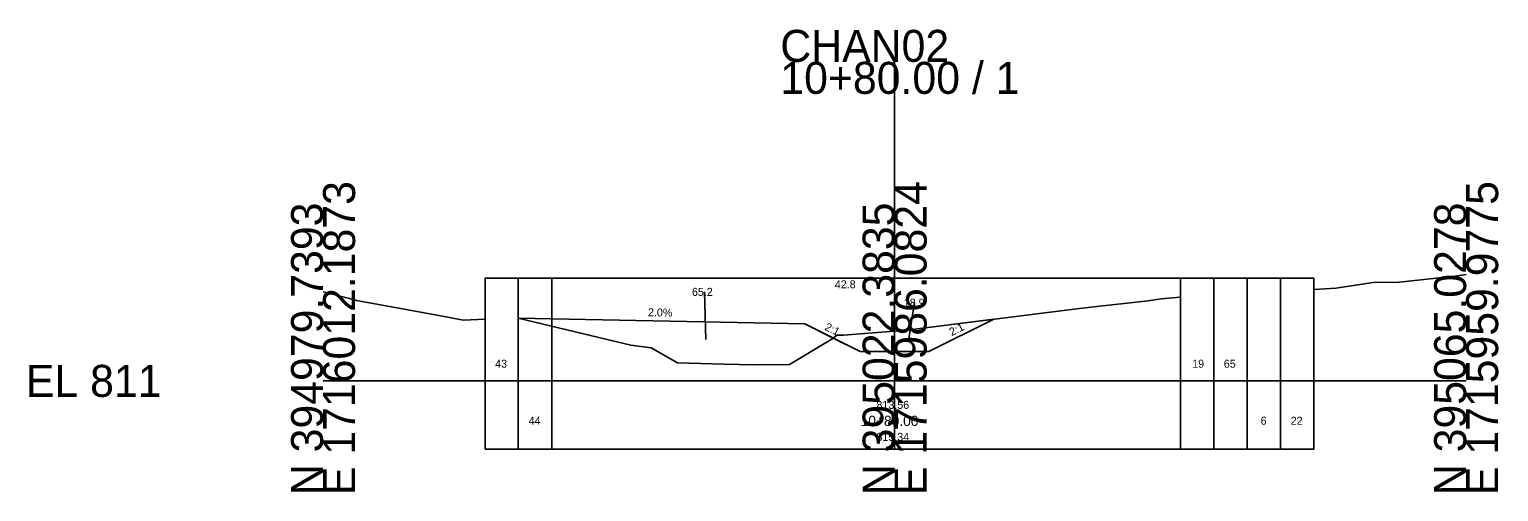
# Model space of a CAD drawing. Extents: x -26 to 103, y -10 to 16052.
# Drawn here: x -25.7 to 102.8, y 10490.3 to 10530.8 of the extents above; entities that cross this region are included whole.
import ezdxf

# ---------------------------------------------------------------- set-up
doc = ezdxf.new("R2010")
doc.units = 0
for name, color, linetype in [('GK_Cells', 7, 'Continuous'), ('SH_Text', 7, 'Continuous'), ('XS_P_Annotation', 7, 'Continuous'), ('XS_P_Boundary', 7, 'Continuous'), ('XS_P_Earthwork_Shapes', 7, 'Continuous'), ('XS_P_Finished_Grade', 7, 'Continuous'), ('XS_X_Ground_Line', 7, 'Continuous')]:
    doc.layers.add(name, color=color, linetype=linetype)

msp = doc.modelspace()

# ---------------------------------------------------------------- linework, layer by layer
at = {"layer": 'GK_Cells'}
for p, q in [((50, 10500), (50, 10527.92)), ((0, 10500), (50, 10500)), ((50, 10500), (100, 10500))]:
    msp.add_line(p, q, dxfattribs=at)
at = {"layer": 'XS_P_Boundary'}
for p, q in [((17.08, 10494.01), (17.08, 10508.99)), ((20, 10494.01), (20, 10508.99)), ((50, 10494.01), (50, 10508.99)), ((75, 10494.01), (75, 10508.99)), ((77.92, 10494.01), (77.92, 10508.99)), ((80.83, 10494.01), (80.83, 10508.99)), ((83.75, 10494.01), (83.75, 10508.99)), ((15.63, 10501.5), (15.63, 10501.5)), ((76.46, 10501.5), (76.46, 10501.5)), ((79.38, 10501.5), (79.38, 10501.5)), ((18.54, 10496.51), (18.54, 10496.51)), ((82.29, 10496.51), (82.29, 10496.51)), ((85.21, 10496.51), (85.21, 10496.51))]:
    msp.add_line(p, q, dxfattribs=at)
msp.add_lwpolyline([(14.17, 10494.01), (14.17, 10508.99), (86.67, 10508.99), (86.67, 10494.01)], close=True, dxfattribs=at)
at = {"layer": 'XS_P_Earthwork_Shapes'}
for p, q in [((33.48, 10503.63), (33.37, 10507.79)), ((51.23, 10503.71), (51.75, 10506.85)), ((42.14, 10504.99), (17.07, 10505.49)), ((44.61, 10503.75), (42.14, 10504.99)), ((58.68, 10505.4), (50.85, 10504.41)), ((53, 10502.56), (58.68, 10505.4)), ((44.63, 10503.74), (47, 10502.56)), ((47, 10502.56), (53, 10502.56))]:
    msp.add_line(p, q, dxfattribs=at)
for points in [[(17.07, 10505.49), (26.93, 10503.12), (28.69, 10502.88), (31.02, 10501.58), (35.08, 10501.45), (36.39, 10501.42), (37.88, 10501.4), (40.81, 10501.44), (44.59, 10503.71)], [(17.08, 10505.49), (42.14, 10504.99), (47, 10502.56), (53, 10502.56), (58.68, 10505.4)], [(44.59, 10503.71), (44.61, 10503.75)], [(50.85, 10504.41), (50, 10504.34), (45.52, 10503.99), (44.94, 10503.99), (44.63, 10503.74)]]:
    msp.add_lwpolyline(points, dxfattribs=at)
at = {"layer": 'XS_P_Finished_Grade'}
for p, q in [((42.14, 10504.99), (17.07, 10505.49)), ((42.14, 10504.99), (47, 10502.56)), ((58.68, 10505.4), (53, 10502.56)), ((47, 10502.56), (53, 10502.56))]:
    msp.add_line(p, q, dxfattribs=at)
at = {"layer": 'XS_X_Ground_Line'}
for points in [[(86.67, 10508), (88.59, 10508.11), (91.86, 10508.6), (94.13, 10508.64), (99.01, 10509.17), (100, 10509.31)], [(0, 10507.8), (2.32, 10507.2), (2.92, 10507.04), (5.67, 10506.53), (10.92, 10505.57), (12.25, 10505.32), (14.17, 10505.39)], [(17.07, 10505.49), (26.93, 10503.12), (28.69, 10502.88), (31.02, 10501.58), (35.08, 10501.45), (36.39, 10501.42), (37.88, 10501.4), (40.81, 10501.44), (44.59, 10503.71), (44.94, 10503.99), (45.52, 10503.99), (50, 10504.34), (50.85, 10504.41), (65.95, 10506.32), (67.16, 10506.46), (72.17, 10507.02), (73.31, 10507.17), (75, 10507.34)]]:
    msp.add_lwpolyline(points, dxfattribs=at)

# ---------------------------------------------------------------- texts
at = {"layer": 'GK_Cells'}
for s, p in [('CHAN02', (40, 10527.92)), ('10+80.00 / 1', (40, 10525.12)), ('EL 811', (-26, 10498.6))]:
    msp.add_text(s, height=2.8, dxfattribs=at).set_placement(p)
for s, p in [('E 1716012.1873', (2.8, 10490)), ('E 1715986.0824', (52.8, 10490)), ('E 1715959.9775', (102.8, 10490)), ('N 394979.7393', (0, 10490)), ('N 395022.3835', (50, 10490)), ('N 395065.0278', (100, 10490))]:
    msp.add_text(s, height=2.8, rotation=90, dxfattribs=at).set_placement(p)
at = {"layer": 'SH_Text'}
for s, p in [('43', (15.05, 10501.15)), ('19', (76.03, 10501.15)), ('65', (78.8, 10501.15)), ('44', (17.98, 10496.16)), ('6', (82.02, 10496.16)), ('22', (84.65, 10496.16))]:
    msp.add_text(s, height=0.7, dxfattribs=at).set_placement(p)
at = {"layer": 'XS_P_Annotation'}
for s, rotation, p in [('2.0%', 358.8542, (28.42, 10505.66)), ('2:1', 333.4349, (43.82, 10504.5)), ('2:1', 26.5651, (54.99, 10503.91))]:
    msp.add_text(s, height=0.7, rotation=rotation, dxfattribs=at).set_placement(p)
for s, height, p in [('813.56', 0.7, (48.41, 10497.55)), ('10+80.00', 0.9, (47.03, 10496.05)), ('815.34', 0.7, (48.41, 10494.75))]:
    msp.add_text(s, height=height, dxfattribs=at).set_placement(p)
at = {"layer": 'XS_P_Earthwork_Shapes'}
for s, p in [('65.2', (32.27, 10507.44)), ('42.8', (44.77, 10508.1)), ('18.9', (50.8, 10506.5))]:
    msp.add_text(s, height=0.7, dxfattribs=at).set_placement(p)

doc.saveas('drawing.dxf')
